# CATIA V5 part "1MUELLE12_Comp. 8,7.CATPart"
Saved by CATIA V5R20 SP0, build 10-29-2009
Part number: 1MUELLE12_Comp. 8,7
Revision: ANY
Definition: UNKNOWN
Nomenclature: 1MUELLE12_Comp. 8,7
Source: Unknown
Bounding box of the stored display mesh (mm): x -7.75 to 7.75, y -7.75 to 7.75, z -0.75 to 9.449
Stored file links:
  C:\Users\Utente\Desktop\IO LAVORO\3D X SITO CF\CUMSA\3D files AE\1MUELLE12_Comp. 8,7.CATPart
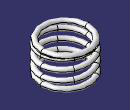
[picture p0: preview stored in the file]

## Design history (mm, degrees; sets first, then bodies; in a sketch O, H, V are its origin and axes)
Set1 "FacciaKO#NONE#16025"
  DatumSurface1 "Sup16025_1"
  Circle1 "Crv16025_1": stored without definition
Set2 "FacciaKO#NONE#6230"
  DatumSurface2 "Sup6230_1"
  Circle2 "Crv6230_1": stored without definition
Set3 "FacciaKO#NONE#13641"
  DatumSurface3 "Sup13641_1"
  Circle3 "Crv13641_1": stored without definition
Set4 "FacciaKO#NONE#16364"
  DatumSurface4 "Sup16364_1"
  Circle4 "Crv16364_1": stored without definition
Body1 "Cortar-Extruir4" (main body)
  Solid1: solid without history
